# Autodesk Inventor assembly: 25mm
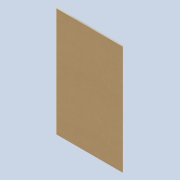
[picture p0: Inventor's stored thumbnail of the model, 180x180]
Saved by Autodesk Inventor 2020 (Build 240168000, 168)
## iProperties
Created: 2020-11
Part Number: 25mm
Document SubType Name: Assembly
Designer: Yolande
Author: Yolande
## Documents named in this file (2)
- D:\Drawing Division\3. Revit Family Files\2. Kraft\25mm.iam
- D:\Drawing Division\3. Revit Family Files\2. Kraft\Lambdaboard 25mm Kraft.ipt
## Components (1 placed, 1 different names)
1. Lambdaboard 25mm Kraft:1
